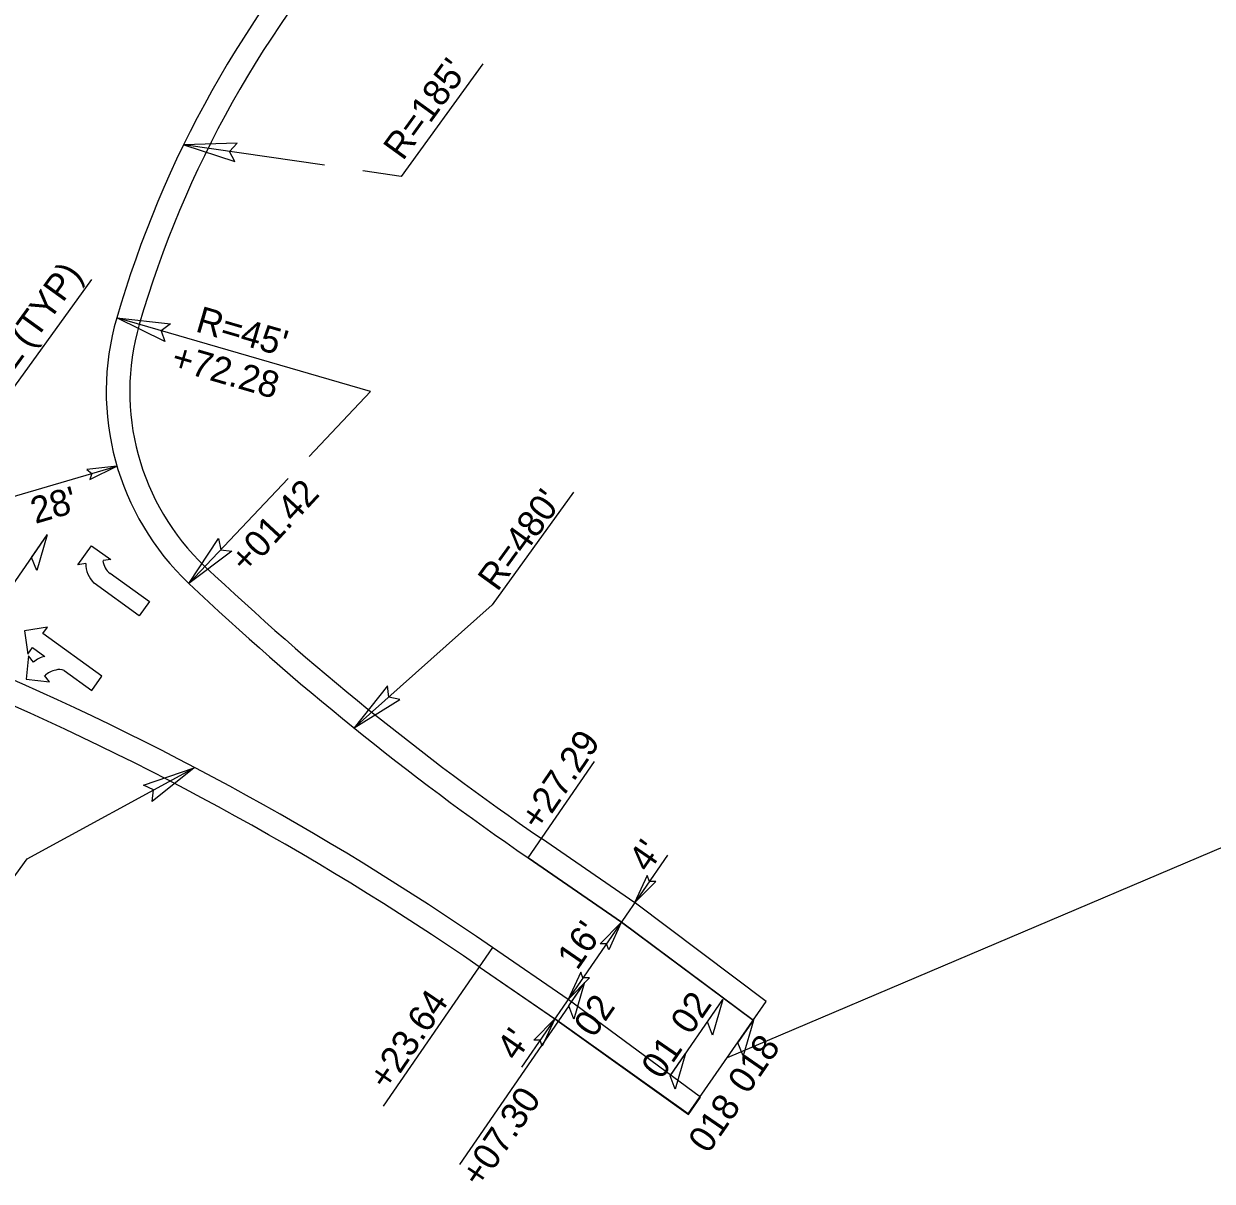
# Model space of a CAD drawing. Extents: x 1183930 to 1185370, y 573068 to 574871.
# Drawn here: x 1184757.1 to 1184959.5, y 574186.1 to 574383.3 of the extents above; entities that cross this region are included whole.
import ezdxf

# ---------------------------------------------------------------- set-up
doc = ezdxf.new("R2010")
doc.units = 0
for name, color, linetype in [('E_NCDOT_Terrain_Model_Contour_Minor', 7, 'Continuous'), ('E_NCDOT_Vertical_Profile_Ground_Line', 7, 'Continuous'), ('P_NCDOT_Horizontal_Alignment', 7, 'Continuous'), ('PC_BEAM', 7, 'Continuous'), ('PC_COLUMN', 7, 'Continuous'), ('PC_OBJECT', 7, 'Continuous'), ('PC_PADFOOTING', 7, 'Continuous'), ('PC_SLAB', 7, 'Continuous'), ('PS_HATCH', 7, 'Continuous')]:
    doc.layers.add(name, color=color, linetype=linetype)

msp = doc.modelspace()

# ---------------------------------------------------------------- linework, layer by layer
for points in [[(1184768.37, 574305.71), (1184772.98, 574307.97), (1184767.84, 574307.4), (1184768.72, 574306.72)], [(1184863.3, 574238.18), (1184861.15, 574233.52), (1184864.78, 574237.2), (1184863.67, 574237.18)], [(1184855.29, 574226.55), (1184858.88, 574230.22), (1184856.74, 574225.52), (1184856.36, 574226.56)], [(1184852, 574221.76), (1184849.84, 574217.09), (1184853.47, 574220.78), (1184852.36, 574220.75)], [(1184843.99, 574210.12), (1184847.58, 574213.8), (1184845.43, 574209.1), (1184845.06, 574210.14)]]:
    msp.add_lwpolyline(points, close=True)
at = {"layer": 'E_NCDOT_Terrain_Model_Contour_Minor'}
for p, q in [((1184835.28, 574376.49), (1184821.41, 574357.32)), ((1184808.31, 574359.24), (1184784.34, 574362.74)), ((1184821.41, 574357.32), (1184814.88, 574358.28)), ((1184752.08, 574316.81), (1184768.7, 574339.76)), ((1184816.15, 574320.66), (1184772.94, 574333.22)), ((1184816.15, 574320.66), (1184805.7, 574309.62)), ((1184802.16, 574305.87), (1184785.22, 574287.98)), ((1184850.75, 574303.5), (1184836.88, 574284.33)), ((1184836.88, 574284.33), (1184813.36, 574263.35)), ((1184757.66, 574241.05), (1184786.24, 574256.6)), ((1184743.79, 574221.88), (1184757.66, 574241.05))]:
    msp.add_line(p, q, dxfattribs=at)
for points in [[(1184793.47, 574362.97), (1184784.34, 574362.74), (1184793.06, 574359.85), (1184792.16, 574361.6)], [(1184781.15, 574329.22), (1184772.94, 574333.22), (1184782.08, 574332.23), (1184780.53, 574331.01)], [(1184792.53, 574293.45), (1184785.22, 574287.98), (1184790.28, 574295.65), (1184790.65, 574293.71)], [(1184819.04, 574270.5), (1184813.36, 574263.35), (1184821.18, 574268.18), (1184819.26, 574268.61)], [(1184777.51, 574253.61), (1184786.15, 574256.55), (1184778.97, 574250.82), (1184779.21, 574252.78)]]:
    msp.add_lwpolyline(points, close=True, dxfattribs=at)
at = {"layer": 'E_NCDOT_Vertical_Profile_Ground_Line'}
for p, q in [((1184861.18, 574233.56), (1184845.29, 574244.5)), ((1184861.18, 574233.56), (1184845.29, 574244.5)), ((1184883.58, 574216.72), (1184861.3, 574233.47)), ((1184883.58, 574216.72), (1184861.3, 574233.47)), ((1184834.69, 574222.66), (1184847.52, 574213.83)), ((1184834.69, 574222.66), (1184847.52, 574213.83)), ((1184847.52, 574213.83), (1184847.57, 574213.79)), ((1184847.52, 574213.83), (1184847.57, 574213.79)), ((1184870.25, 574197.57), (1184847.57, 574213.79)), ((1184847.57, 574213.79), (1184870.25, 574197.57))]:
    msp.add_line(p, q, dxfattribs=at)
for centre, radius, start, end in [((1184950.59, 574281.59), 181, 137.7604, 163.7957), ((1184950.59, 574281.59), 181, 137.7604, 163.7957), ((1184816.15, 574320.66), 41, 163.7957, 226.5759), ((1184816.15, 574320.66), 41, 163.7957, 226.5759), ((1185115.17, 574636.59), 476, 226.5759, 235.4598), ((1185115.17, 574636.59), 476, 226.5759, 235.4598), ((1184553.46, 573814.09), 496, 55.4598, 67.5035), ((1184553.46, 573814.09), 496, 55.4598, 67.5035)]:
    msp.add_arc(centre, radius, start, end, dxfattribs=at)
at = {"layer": 'P_NCDOT_Horizontal_Alignment'}
for p, q in [((1184858.91, 574230.26), (1184843.02, 574241.2)), ((1184858.91, 574230.26), (1184843.02, 574241.2)), ((1184881.38, 574213.52), (1184858.91, 574230.26)), ((1184881.38, 574213.52), (1184858.91, 574230.26)), ((1184849.84, 574217.08), (1184836.96, 574225.95)), ((1184849.84, 574217.08), (1184836.96, 574225.95)), ((1184872.37, 574200.43), (1184849.84, 574217.08)), ((1184872.37, 574200.43), (1184849.84, 574217.08)), ((1184870.25, 574197.57), (1184883.58, 574216.72))]:
    msp.add_line(p, q, dxfattribs=at)
for centre, radius, start, end in [((1184950.59, 574281.59), 185, 137.7604, 163.7957), ((1184816.15, 574320.66), 45, 163.7957, 226.5759), ((1185115.17, 574636.59), 480, 226.5759, 235.4598), ((1184553.46, 573814.09), 500, 55.4598, 67.5035)]:
    msp.add_arc(centre, radius, start, end, dxfattribs=at)
at = {"layer": 'PC_BEAM'}
for p, q in [((1184766.34, 574291.17), (1184768.63, 574294.41)), ((1184768.63, 574294.41), (1184771.93, 574292.07)), ((1184771.93, 574292.07), (1184770.61, 574291.86)), ((1184767.66, 574291.38), (1184766.34, 574291.17)), ((1184776.76, 574282.46), (1184769.07, 574288.03)), ((1184771.83, 574289.7), (1184778.5, 574284.87)), ((1184778.5, 574284.87), (1184776.76, 574282.46)), ((1184761.15, 574280.53), (1184757.22, 574279.87)), ((1184757.22, 574279.87), (1184757.82, 574275.93)), ((1184760.35, 574279.43), (1184761.15, 574280.53)), ((1184770.41, 574272.15), (1184760.35, 574279.43)), ((1184757.82, 574275.93), (1184758.61, 574277.03)), ((1184758.61, 574277.03), (1184760.69, 574275.52)), ((1184757.93, 574275.63), (1184757.51, 574271.66)), ((1184758.78, 574274.57), (1184757.93, 574275.63)), ((1184757.51, 574271.66), (1184761.47, 574271.23)), ((1184761.47, 574271.23), (1184760.66, 574272.26)), ((1184763.97, 574273.15), (1184768.67, 574269.75)), ((1184768.67, 574269.75), (1184770.41, 574272.15))]:
    msp.add_line(p, q, dxfattribs=at)
for centre, radius, start, end in [((1184773.54, 574292.08), 2.95, 184.4449, 234.103), ((1184772.38, 574291.39), 4.73, 180.1153, 225.427), ((1184761.48, 574271.62), 3.99, 101.6336, 132.5122), ((1184763.36, 574269.31), 3.99, 101.5398, 132.3934), ((1184763.15, 574271.03), 2.27, 68.7179, 105.0299)]:
    msp.add_arc(centre, radius, start, end, dxfattribs=at)
at = {"layer": 'PC_COLUMN'}
for points in [[(1184761.06, 574296.23), (1184759.31, 574290.15), (1184758.44, 574292.42)], [(1184852.55, 574219.79), (1184850.8, 574213.72), (1184849.93, 574215.98)], [(1184876.19, 574217.1), (1184874.44, 574211.02), (1184873.57, 574213.29)], [(1184881.38, 574213.52), (1184879.63, 574207.45), (1184878.76, 574209.71)], [(1184869.85, 574207.89), (1184868.09, 574201.81), (1184867.23, 574204.08)]]:
    msp.add_lwpolyline(points, close=True, dxfattribs=at)
at = {"layer": 'PC_OBJECT'}
for p, q in [((1184861.18, 574233.56), (1184861.3, 574233.47)), ((1184849.84, 574217.08), (1184836.96, 574225.95)), ((1184834.69, 574222.66), (1184847.57, 574213.79)), ((1184872.37, 574200.43), (1184849.84, 574217.08)), ((1184847.57, 574213.79), (1184870.35, 574197.5)), ((1184870.35, 574197.5), (1184872.37, 574200.43))]:
    msp.add_line(p, q, dxfattribs=at)
msp.add_lwpolyline([(1184843.02, 574241.2), (1184858.91, 574230.26), (1184881.36, 574213.53), (1184883.58, 574216.72), (1184861.3, 574233.47), (1184861.18, 574233.56), (1184845.29, 574244.5)], dxfattribs=at)
for centre, radius, start, end in [((1184950.59, 574281.59), 185, 137.7604, 163.7957), ((1184950.59, 574281.59), 181, 137.7604, 163.7957), ((1184816.15, 574320.66), 45, 163.7957, 226.5759), ((1184816.15, 574320.66), 41, 163.7957, 226.5759), ((1185115.17, 574636.59), 476, 226.5759, 235.4598), ((1185115.17, 574636.59), 480, 226.5759, 235.4598), ((1184553.46, 573814.09), 500, 55.4598, 67.5035), ((1184553.46, 573814.09), 496, 55.4598, 67.5035)]:
    msp.add_arc(centre, radius, start, end, dxfattribs=at)
at = {"layer": 'PC_PADFOOTING'}
for p, q in [((1184746.12, 574300.07), (1184772.98, 574307.97)), ((1184843.02, 574241.2), (1184854.33, 574257.64)), ((1184866.76, 574241.67), (1184841.91, 574205.57)), ((1184836.96, 574225.95), (1184818.34, 574198.91)), ((1184849.93, 574215.98), (1184831.32, 574188.94))]:
    msp.add_line(p, q, dxfattribs=at)
at = {"layer": 'PC_SLAB'}
for p, q in [((1184747.52, 574276.55), (1184761.12, 574296.31)), ((1184850.4, 574216.67), (1184852.68, 574219.98)), ((1184867.26, 574204.12), (1184876.19, 574217.1))]:
    msp.add_line(p, q, dxfattribs=at)
at = {"layer": 'PS_HATCH'}
msp.add_line((1184876.95, 574207.19), (1185286.85, 574381.4), dxfattribs=at)

# ---------------------------------------------------------------- texts
at = {"layer": 'E_NCDOT_Terrain_Model_Contour_Minor'}
for s, rotation, p in [("R=185'", 54.103, (1184821.69, 574359.86)), ("R=2'(TYP)", 54.103, (1184750.82, 574317.85)), ("R=45'", 343.7957, (1184786.17, 574330.96)), ('+72.28', 343.7957, (1184781.96, 574324.59)), ('+01.42', 47.2356, (1184795.08, 574289.44)), ("R=480'", 54.103, (1184837.78, 574286.43))]:
    msp.add_text(s, height=4.5, rotation=rotation, dxfattribs=at).set_placement(p)
at = {"layer": 'PC_PADFOOTING'}
for s, rotation, p in [("28'", 16.3782, (1184759.07, 574298.1)), ('+27.29', 55.717, (1184845, 574245.6)), ("4'", 55.4598, (1184863.53, 574238.52)), ("16'", 55.4598, (1184851.38, 574221.89)), ('+23.64', 55.8157, (1184819.17, 574201.34)), ("4'", 55.4598, (1184841.04, 574206.4)), ('+07.30', 55.8157, (1184834.93, 574184.77))]:
    msp.add_text(s, height=4.5, rotation=rotation, dxfattribs=at).set_placement(p)
at = {"layer": 'PC_SLAB'}
for s, p in [('02', (1184854.21, 574210.36)), ('02', (1184870.67, 574210.84)), ('018', (1184880.43, 574200.75)), ('01', (1184865.69, 574203.24)), ('018', (1184873.69, 574190.62))]:
    msp.add_text(s, height=4.5, rotation=55.4598, dxfattribs=at).set_placement(p)

doc.saveas('drawing.dxf')
